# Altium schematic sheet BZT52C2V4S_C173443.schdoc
size 127 x 101 mm
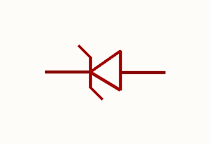
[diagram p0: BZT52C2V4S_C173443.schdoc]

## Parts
D?  bzt52c2v4s_c173443  [SOD-323_L1.8-W1.3-LS2.5-RD]  (value not drawn)

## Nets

Not connected (* = marked no-connect by the designer): D? 1 2

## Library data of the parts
D? = bzt52c2v4s_c173443: 二极管配置:1个独立式;稳压值(标称值):2.4V;稳压值(范围):2.28V~2.56V;耗散功率(Pd):200mW;; Manufacturer: MDD(辰达半导体); AddInBom: yes; ModelId: db63db13d9e342eb939127d413d6200b; ModelTransform: 104.3305,51.181,0,0,0,0,0,-0.004,0; Diode Configuration: 1个独立式; Zener Voltage(Nom): 2.4V; Reverse Leakage Current (Ir): 120uA@1V; Pd - Power Dissipation: 200mW; Impedance(Zzt): 100Ω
